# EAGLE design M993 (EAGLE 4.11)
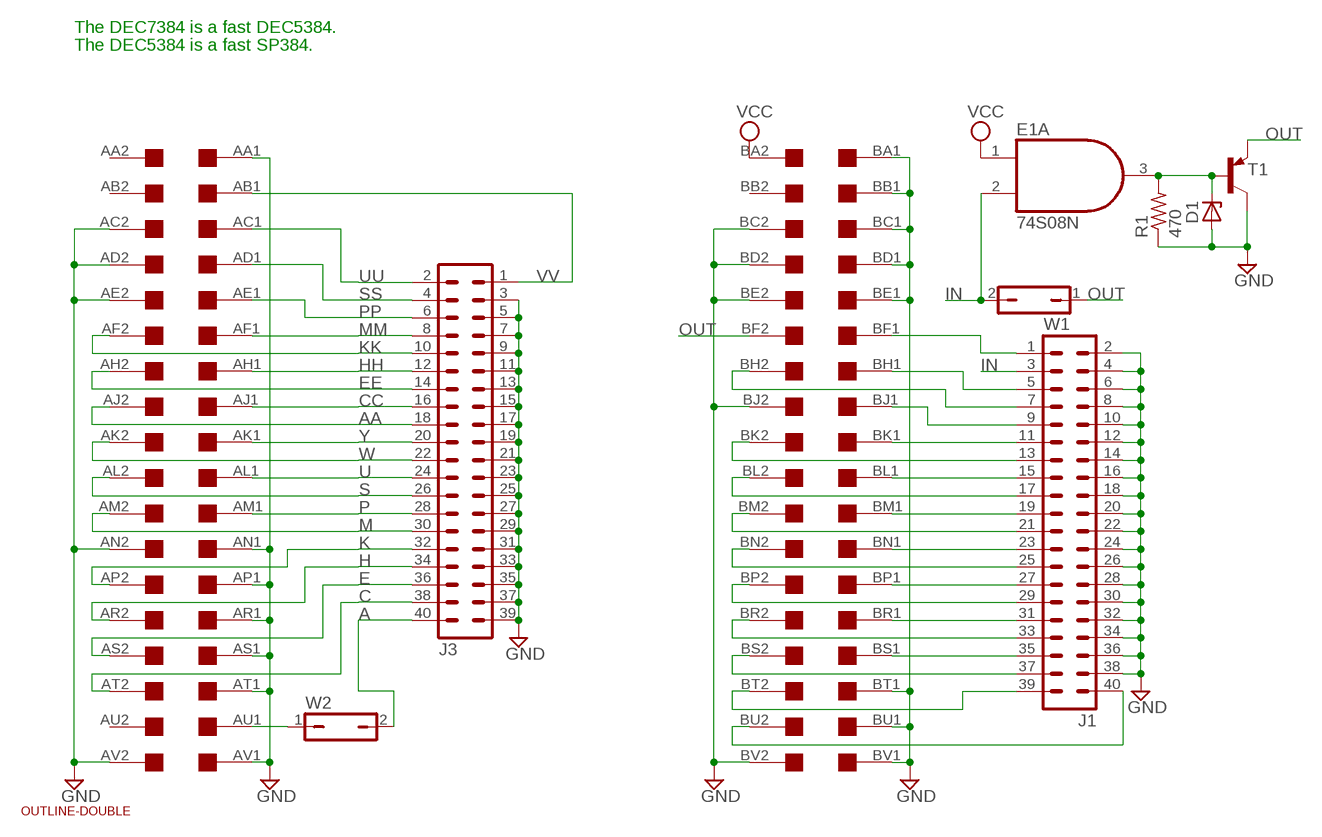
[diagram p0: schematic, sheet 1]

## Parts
D1  ZENER-DIODEZD-10  [ZDIO-10]
E1  74S08N  [DIL14]
J1  MA20-2  [MA20-2]
J3  MA20-2  [MA20-2]
R1  470  R-US_0207/10  [0207/10]
T1  -PNP-TO92  [TO92]
U$1  OUTLINE-DOUBLE  [DOUBLE]
U$2  DOUBLE  [EDGE-CON4]
W1  JP1Q  [JP1]
W2  JP1Q  [JP1]

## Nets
A: J3.40 W2.2
AA: J3.18 U$2.AJ2
C: J3.38 U$2.AT2
CC: J3.16 U$2.AJ1
E: J3.36 U$2.AS2
EE: J3.14 U$2.AH2
GND: D1.A J1.2 J1.4 J1.6 J1.8 J1.10 J1.12 J1.14 J1.16 J1.18 J1.20 J1.22 J1.24 J1.26 J1.28 J1.30 J1.32 J1.34 J1.36 J1.38 J3.3 J3.5 J3.7 J3.9 J3.11 J3.13 J3.15 J3.17 J3.19 J3.21 J3.23 J3.25 J3.27 J3.29 J3.31 J3.33 J3.35 J3.37 J3.39 R1.1 T1.3(C) U$2.AA1 U$2.AC2 U$2.AD2 U$2.AE2 U$2.AN1 U$2.AN2 U$2.AP1 U$2.AR1 U$2.AS1 U$2.AT1 U$2.AV1 U$2.AV2 U$2.BA1 U$2.BB1 U$2.BC1 U$2.BC2 U$2.BD1 U$2.BD2 U$2.BE1 U$2.BE2 U$2.BJ2 U$2.BT1 U$2.BU1 U$2.BV1 U$2.BV2
H: J3.34 U$2.AR2
HH: J3.12 U$2.AH1
IN: E1.2(A:I1) J1.3 W1.2
K: J3.32 U$2.AP2
KK: J3.10 U$2.AF2
M: J3.30 U$2.AM2
MM: J3.8 U$2.AF1
N$1: U$2.AU1 W2.1
N$2: D1.C E1.3(A:O) R1.2 T1.2(B)
N$3: J1.37 U$2.BS2
N$4: J1.35 U$2.BS1
N$5: J1.33 U$2.BR2
N$6: J1.31 U$2.BR1
N$7: J1.29 U$2.BP2
N$8: J1.27 U$2.BP1
N$9: J1.25 U$2.BN2
N$10: J1.40 U$2.BU2
N$11: J1.39 U$2.BT2
N$12: J1.23 U$2.BN1
N$13: J1.21 U$2.BM2
N$14: J1.19 U$2.BM1
N$15: J1.17 U$2.BL2
N$16: J1.15 U$2.BL1
N$17: J1.13 U$2.BK2
N$18: J1.11 U$2.BK1
N$19: J1.9 U$2.BJ1
N$20: J1.7 U$2.BH2
N$21: J1.5 U$2.BH1
N$23: J1.1 U$2.BF1
OUT: T1.1(E) U$2.BF2 W1.1
P: J3.28 U$2.AM1
PP: J3.6 U$2.AE1
S: J3.26 U$2.AL2
SS: J3.4 U$2.AD1
U: J3.24 U$2.AL1
UU: J3.2 U$2.AC1
VCC: E1.1(A:I0) U$2.BA2
VV: J3.1 U$2.AB1
W: J3.22 U$2.AK2
Y: J3.20 U$2.AK1
Unconnected: E1.4(B:I0) E1.5(B:I1) E1.6(B:O) E1.8(C:O) E1.9(C:I0) E1.10(C:I1) E1.11(D:O) E1.12(D:I0) E1.13(D:I1) U$2.AA2 U$2.AB2 U$2.AU2 U$2.BB2

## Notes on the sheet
- The DEC7384 is a fast DEC5384.
- The DEC5384 is a fast SP384.

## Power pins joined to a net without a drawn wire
GND: E1.7(P:GND)
VCC: E1.14(P:VCC)

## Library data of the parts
D1 = diode:ZENER-DIODE: Z-Diode
E1 = 74xx-us:74*08: Quad 2-input AND gate
J1 J3 = con-lstb:MA20-2: PIN HEADER
R1 = rcl:R-US_: RESISTOR, American symbol
T1 = transistor:*-PNP-: PNP Transistror
U$1 = dec-con:OUTLINE-*: Board outlines for DEC boards.
U$2 = dec-con:DOUBLE: Double-Height DEC board
W1 W2 = jumper:JP1Q: JUMPER

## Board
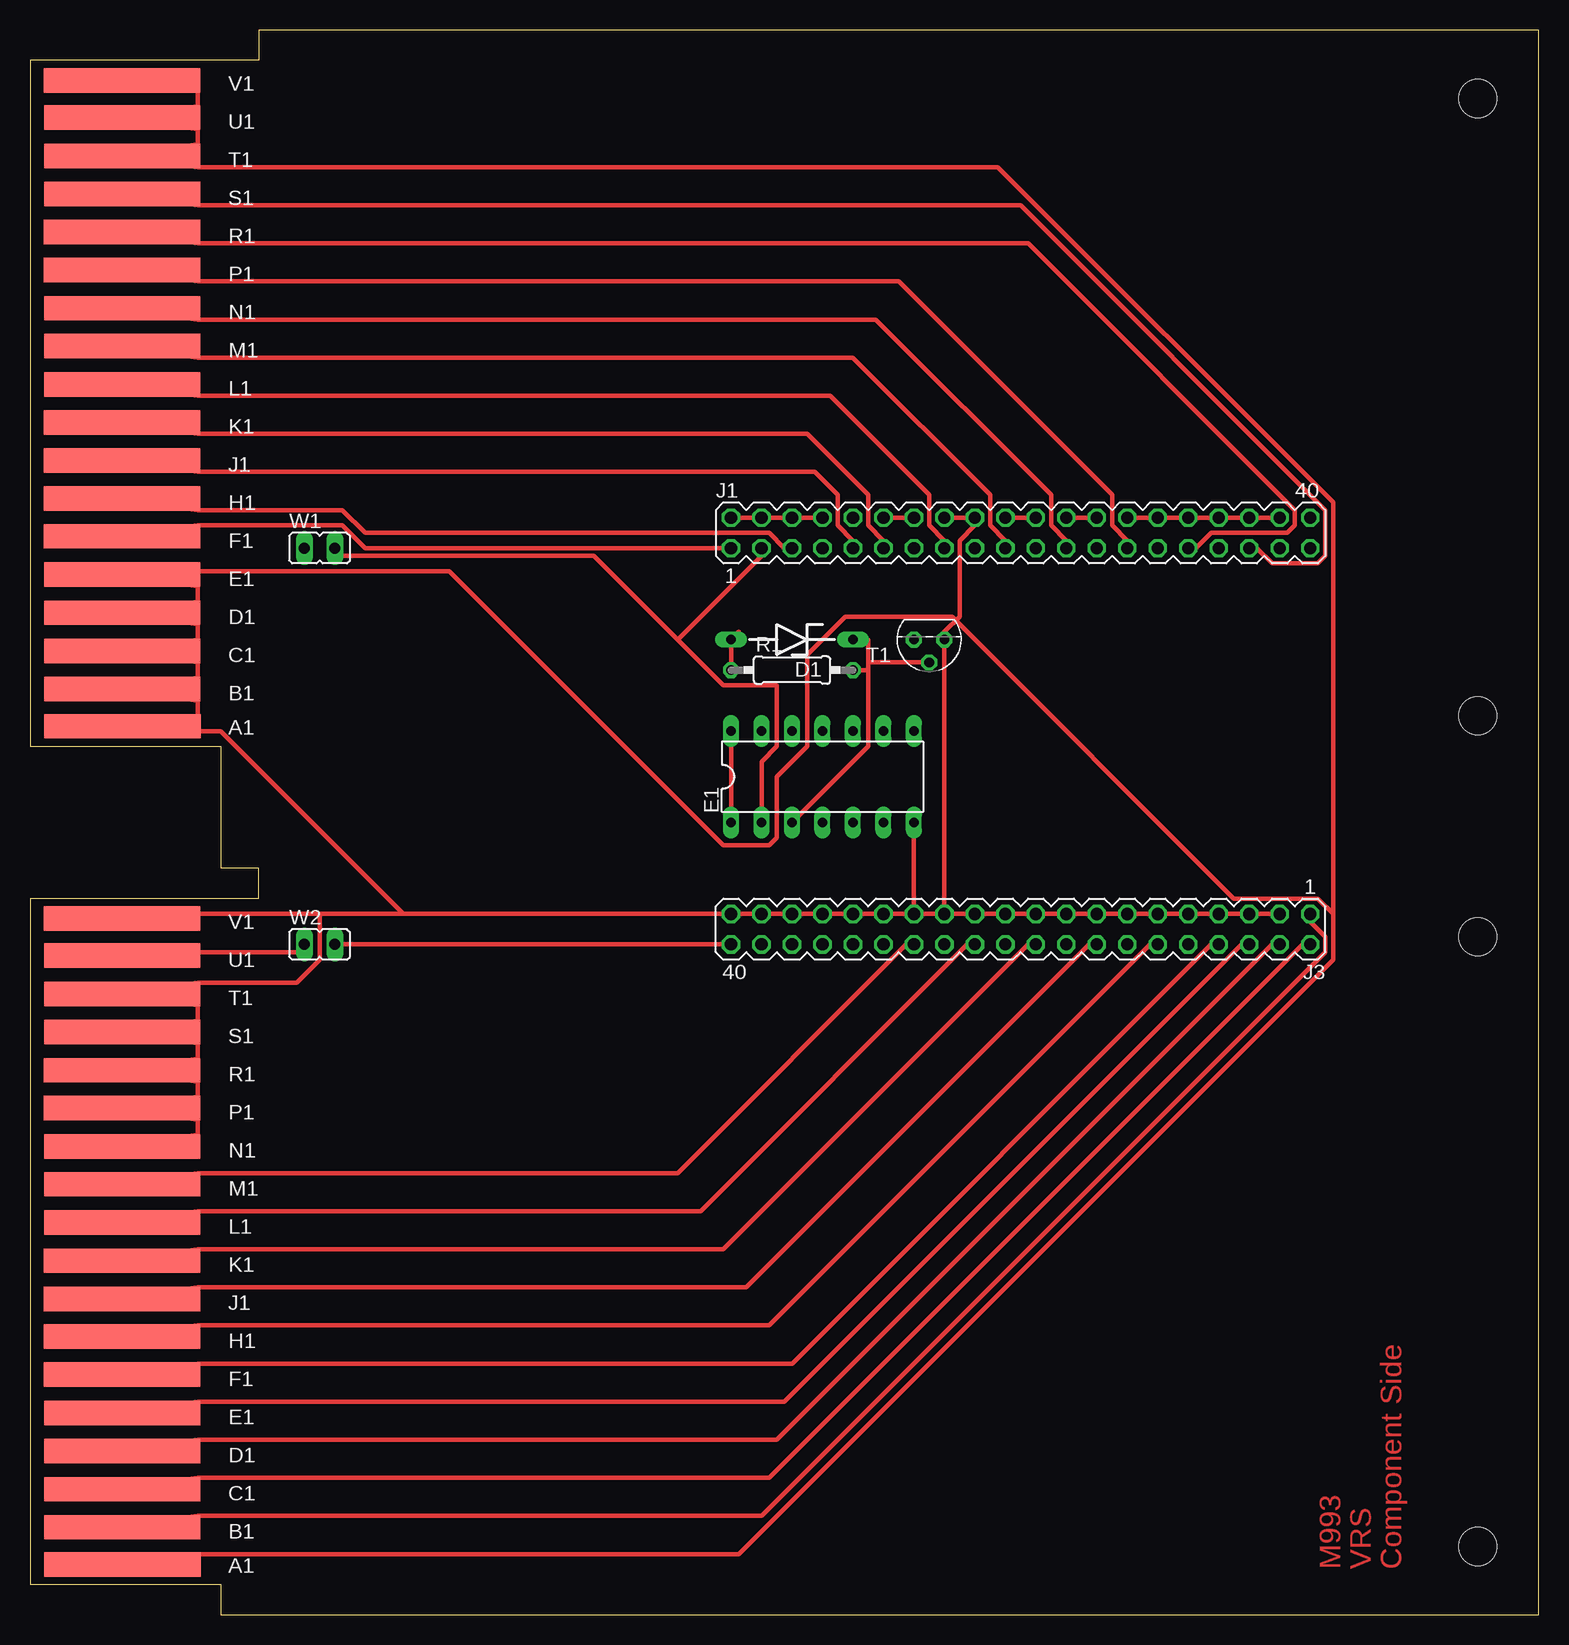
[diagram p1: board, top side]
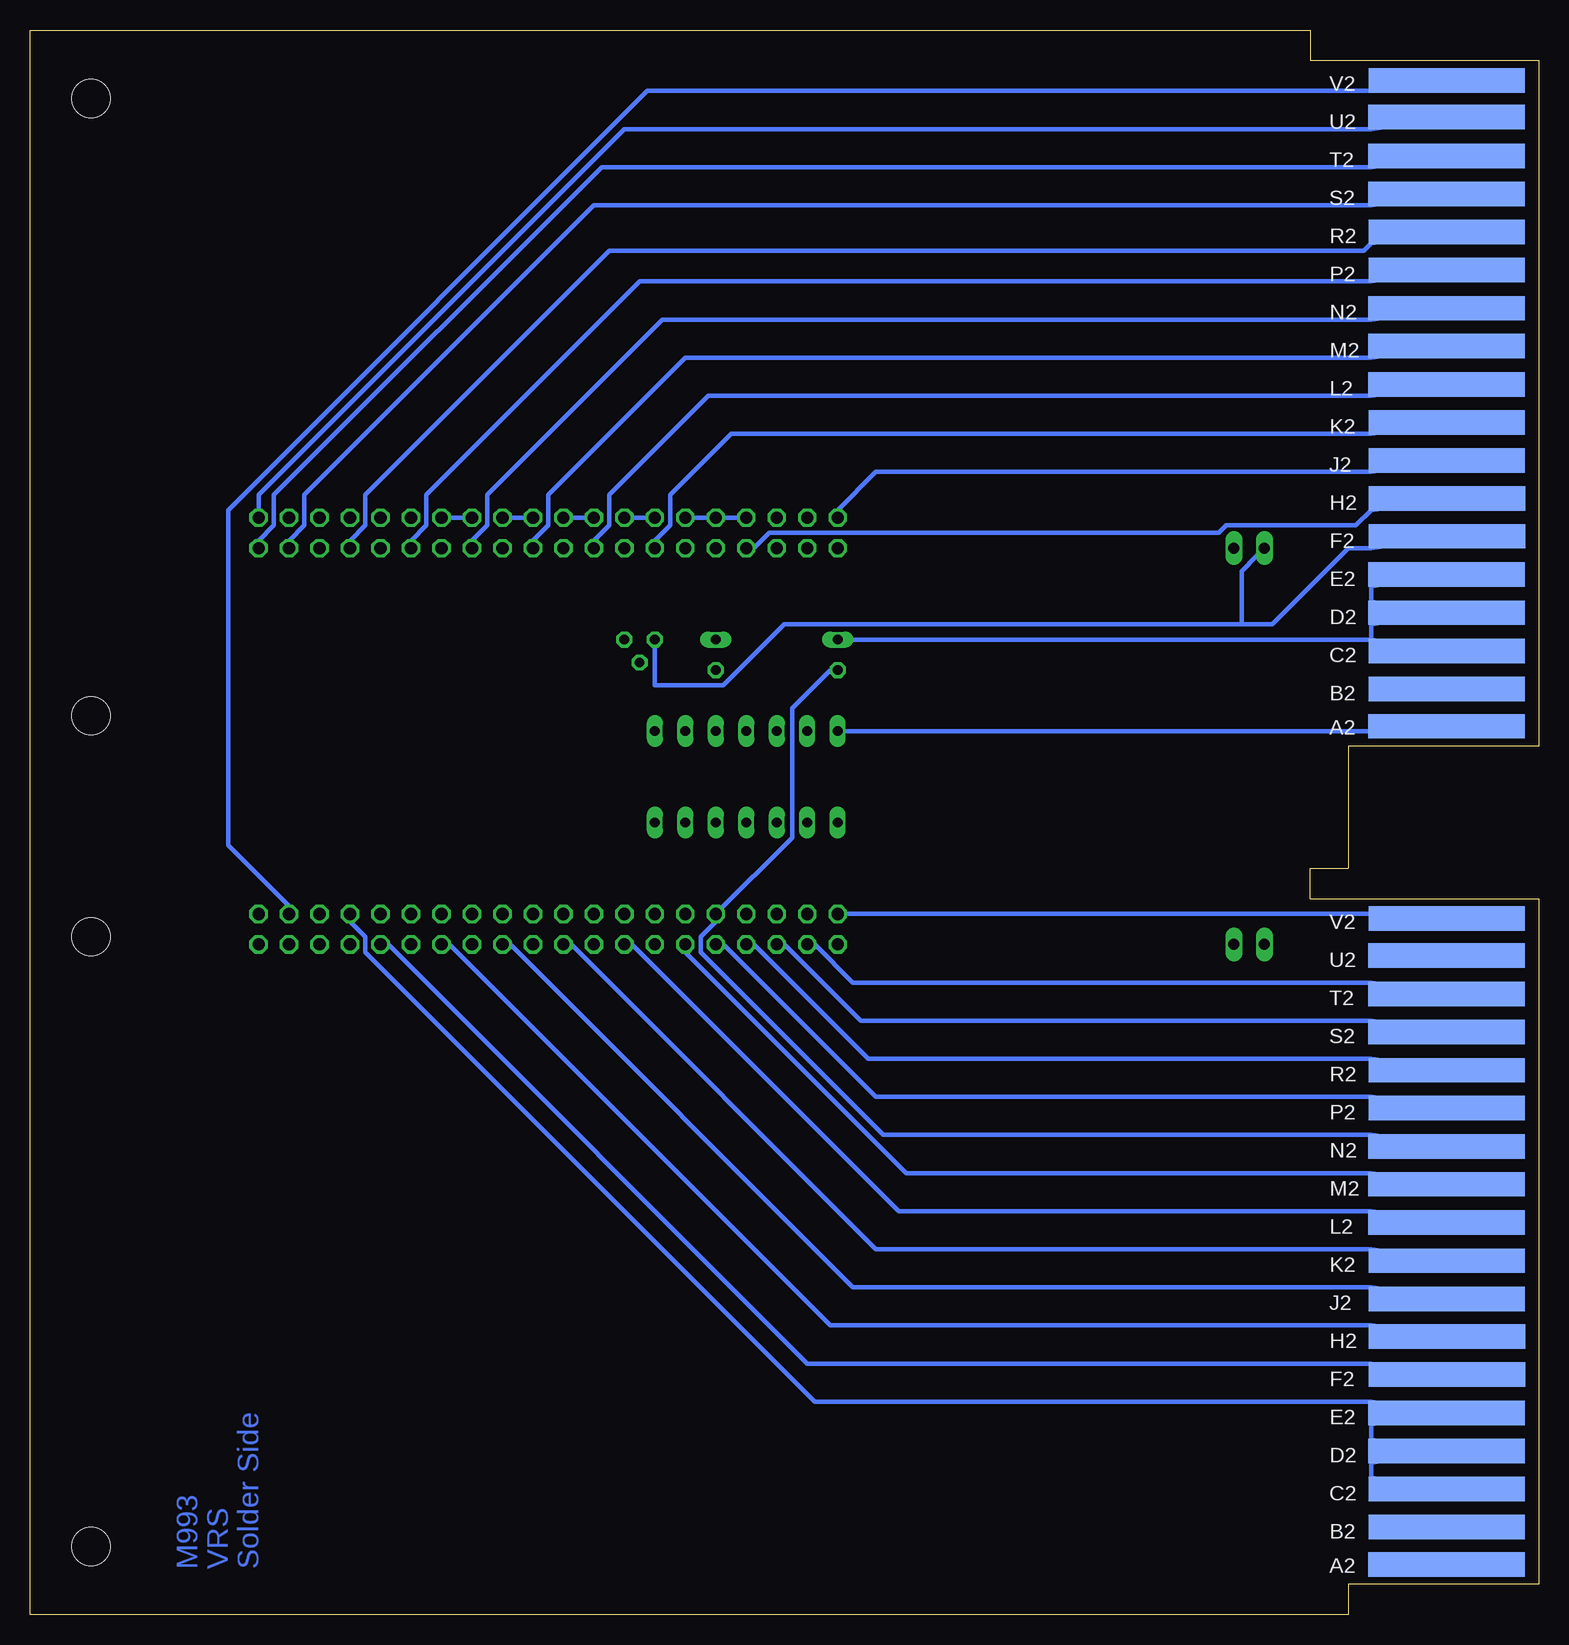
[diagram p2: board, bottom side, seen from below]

Size 125.73 x 132.08 mm. Coordinates in mm from the lower left corner, seen from the top.
Copper layers (1*16): Top 0.035mm / dielectric 1.5mm / Bottom 0.035mm
Design rules "default": minimum track width 15mil, minimum drill 24mil, track to track 8mil, track to pad 8mil, pad to pad 8mil, via to via 8mil, smd to smd 8mil, copper to edge 25mil, drill to drill 8mil, minimum pad ring 10mil, minimum via ring 8mil, stop-mask expansion 4mil, vias tented up to drill 0mil, thermal gap 10mil

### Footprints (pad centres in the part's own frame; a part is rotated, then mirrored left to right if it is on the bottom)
ZDIO-10 = drill 0.813 long: A 5.08,0; C -5.08,0
DIL14 = drill 0.813 long: 1 -7.62,-3.81; 2 -5.08,-3.81; 3 -2.54,-3.81; 4 0,-3.81; 5 2.54,-3.81; 6 5.08,-3.81; 7 7.62,-3.81; 8 7.62,3.81; 9 5.08,3.81; 10 2.54,3.81; 11 0,3.81; 12 -2.54,3.81; 13 -5.08,3.81; 14 -7.62,3.81
MA20-2 = drill 1.016 octagon: 1 -24.13,-1.27; 2 -24.13,1.27; 3 -21.59,-1.27; 4 -21.59,1.27; 5 -19.05,-1.27; 6 -19.05,1.27; 7 -16.51,-1.27; 8 -16.51,1.27; 9 -13.97,-1.27; 10 -13.97,1.27; 11 -11.43,-1.27; 12 -11.43,1.27; 13 -8.89,-1.27; 14 -8.89,1.27; 15 -6.35,-1.27; 16 -6.35,1.27; 17 -3.81,-1.27; 18 -3.81,1.27; 19 -1.27,-1.27; 20 -1.27,1.27; 21 1.27,-1.27; 22 1.27,1.27; 23 3.81,-1.27; 24 3.81,1.27; 25 6.35,-1.27; 26 6.35,1.27; 27 8.89,-1.27; 28 8.89,1.27; 29 11.43,-1.27; 30 11.43,1.27; 31 13.97,-1.27; 32 13.97,1.27; 33 16.51,-1.27; 34 16.51,1.27; 35 19.05,-1.27; 36 19.05,1.27; 37 21.59,-1.27; 38 21.59,1.27; 39 24.13,-1.27; 40 24.13,1.27
0207/10 = drill 0.813 octagon: 1 -5.08,0; 2 5.08,0
TO92 = drill 0.813 octagon: 1 1.27,0; 2 0,1.905; 3 -1.27,0
DOUBLE = hole 3.175: 120.65,56.515; 120.65,5.715; 120.65,74.93; 120.65,126.365
EDGE-CON4 = smd 13.017 x 2.032: AA1 7.709,4.207; AB1 7.684,7.312; AC1 7.684,10.474; AD1 7.684,13.665; AE1 7.693,16.84; AF1 7.668,20.041; AH1 7.668,23.19; AJ1 7.668,26.34; AK1 7.668,29.515; AL1 7.693,32.69; AM1 7.693,35.89; AN1 7.693,39.04; AP1 7.668,42.24; AR1 7.668,45.39; AS1 7.693,48.565; AT1 7.693,51.74; AU1 7.693,54.94; AV1 7.668,58.026; BA1 7.709,74.057; BB1 7.684,77.162; BC1 7.684,80.324; BD1 7.684,83.515; BE1 7.693,86.69; BF1 7.668,89.891; BH1 7.668,93.04; BJ1 7.668,96.19; BK1 7.668,99.365; BL1 7.693,102.54; BM1 7.693,105.74; BN1 7.693,108.89; BP1 7.668,112.09; BR1 7.668,115.24; BS1 7.693,118.415; BT1 7.693,121.59; BU1 7.693,124.79; BV1 7.668,127.876 | smd 13.017 x 2.032 bottom: AA2 7.69,4.207; AB2 7.668,7.328; AC2 7.668,10.49; AD2 7.693,13.665; AE2 7.693,16.84; AF2 7.642,20.041; AH2 7.642,23.19; AJ2 7.668,26.34; AK2 7.668,29.515; AL2 7.693,32.69; AM2 7.693,35.89; AN2 7.693,39.04; AP2 7.668,42.24; AR2 7.668,45.39; AS2 7.693,48.565; AT2 7.693,51.74; AU2 7.693,54.966; AV2 7.668,58.026; BA2 7.69,74.057; BB2 7.668,77.178; BC2 7.668,80.34; BD2 7.693,83.515; BE2 7.693,86.69; BF2 7.642,89.891; BH2 7.642,93.04; BJ2 7.668,96.19; BK2 7.668,99.365; BL2 7.693,102.54; BM2 7.693,105.74; BN2 7.693,108.89; BP2 7.668,112.09; BR2 7.668,115.24; BS2 7.693,118.415; BT2 7.693,121.59; BU2 7.693,124.816; BV2 7.668,127.876
JP1 = drill 0.914 long: 1 0,-1.27; 2 0,1.27

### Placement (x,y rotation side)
D1  63.5,81.28 180 top
E1  66.04,69.85 0 top
J1  82.55,90.17 0 top
J3  82.55,57.15 180 top
R1  63.5,78.74 0 top
T1  74.93,81.28 180 top
U$1  0,0 0 top
U$2  0,0 0 top
W1  24.13,88.9 270 top
W2  24.13,55.88 270 top

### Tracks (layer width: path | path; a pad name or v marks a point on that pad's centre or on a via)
A
  Top 0.381: W2.2 26.04,55.88 57.79,55.88 J3.40
AA
  Bottom 0.381: J3.18 85.73,55.88 57.15,27.3 13.97,27.3 U$2.AJ2
C
  Bottom 0.381: J3.38 60.33,55.88 57.15,52.7 13.97,52.7 U$2.AT2
CC
  Top 0.381: J3.16 88.27,55.88 59.69,27.3 13.97,27.3 U$2.AJ1
E
  Bottom 0.381: J3.36 62.87,55.88 56.52,49.53 13.97,49.53 U$2.AS2
EE
  Bottom 0.381: J3.14 90.81,55.88 59.06,24.13 13.97,24.13 U$2.AH2
GND
  Top 0.381: U$2.BV1 13.97,127 13.97,125.73 U$2.BU1 13.97,123.83 13.97,122.56 U$2.BT1 13.97,120.65 80.65,120.65 108.59,92.71 108.59,58.42 | R1.1 D1.A 59.06,81.92 | J3.27 E1.7 | J3.27 J3.25 | J3.25 J3.23 J3.21 J3.19 J3.17 J3.15 J3.13 J3.11 J3.9 J3.7 J3.5 J3.3 | J3.27 J3.29 J3.31 J3.33 J3.35 J3.37 J3.39 31.12,58.42 | 31.12,58.42 24.13,58.42 | 24.13,58.42 13.97,58.42 U$2.AV2 | U$2.AA1 13.97,5.08 59.06,5.08 108.59,54.61 108.59,58.42 | 31.12,58.42 15.88,73.66 13.97,73.66 U$2.BA1 13.97,74.93 13.97,76.2 U$2.BB1 13.97,78.11 13.97,79.38 U$2.BC1 13.97,81.28 13.97,82.55 U$2.BD1 13.97,84.45 13.97,85.72 U$2.BE1 13.97,87 34.93,87 57.79,64.14 61.6,64.14 62.23,64.77 62.23,69.85 64.77,72.39 64.77,80.01 67.95,83.19 76.84,83.19 100.33,59.69 107.32,59.69 108.59,58.42 | 24.13,58.42 24.13,54.61 22.23,52.7 13.97,52.7 U$2.AT1 13.97,50.8 13.97,49.53 U$2.AS1 13.97,47.62 13.97,46.35 U$2.AR1 13.97,44.45 13.97,43.18 U$2.AP1 13.97,41.27 13.97,40.01 U$2.AN2 | J3.25 T1.3 76.2,81.92 77.47,83.19 77.47,89.53 78.74,90.81 J1.18 J1.16 | J1.2 J1.4 J1.6 J1.8 | J1.14 J1.12 | J1.20 J1.22 | J1.24 J1.26 | J1.28 J1.30 J1.32 J1.34 J1.36 J1.38
  Bottom 0.381: 13.97,81.28 13.97,82.55 U$2.BD2 13.97,84.45 13.97,85.72 U$2.BE1 | U$2.BJ2 13.97,95.25 55.25,95.25 58.42,92.08 J1.2 | 13.97,81.28 U$2.BC2 | D1.A 13.97,81.28 | U$2.AC2 13.97,11.43 13.97,12.7 U$2.AD2 13.97,14.61 13.97,15.88 U$2.AE2 13.97,17.78 60.33,17.78 97.79,55.24 97.79,56.52 99.06,57.78 J3.7 | U$2.AV2 13.97,58.42 J3.39 | U$2.AN2 13.97,40.01 54.61,40.01 69.85,55.24 69.85,56.52 68.58,57.78 J3.31 62.23,64.77 62.23,75.56 59.06,78.74 R1.1 | U$2.BV1 13.97,127 74.3,127 109.22,92.08 109.22,64.14 104.14,59.05 J3.3 | J1.8 J1.10 J1.12 | J1.16 J1.14 | J1.18 J1.20 | J1.22 J1.24 | J1.26 J1.28
H
  Bottom 0.381: J3.34 65.41,55.88 55.88,46.35 13.97,46.35 U$2.AR2
HH
  Top 0.381: J3.12 93.35,55.88 61.6,24.13 13.97,24.13 U$2.AH1
IN
  Top 0.381: 53.98,81.28 46.99,88.27 26.04,88.27 W1.2 | 53.98,81.28 57.79,77.47 62.23,77.47 62.23,72.39 60.96,71.12 60.96,67.31 E1.2 | 53.98,81.28 60.96,88.27 J1.3
K
  Bottom 0.381: J3.32 67.95,55.88 55.25,43.18 13.97,43.18 U$2.AP2
KK
  Bottom 0.381: J3.10 95.89,55.88 60.96,20.95 13.97,20.95 U$2.AF2
M
  Bottom 0.381: J3.30 71.12,55.24 52.71,36.83 13.97,36.83 U$2.AM2
MM
  Top 0.381: J3.8 98.43,55.88 63.5,20.95 13.97,20.95 U$2.AF1
N$1
  Top 0.381: W2.1 22.23,55.24 13.97,55.24 U$2.AU1
N$2
  Top 0.381: 69.85,79.38 69.85,81.28 D1.C | 69.85,78.74 69.85,79.38 | 69.85,78.74 69.85,72.39 64.14,66.67 E1.3 | 69.85,78.74 69.22,78.74 R1.2 | 69.85,79.38 74.3,79.38 T1.2
N$3
  Bottom 0.381: U$2.BS2 13.97,117.47 78.74,117.47 102.87,93.34 102.87,90.81 104.14,89.53 J1.37
N$4
  Top 0.381: U$2.BS1 13.97,117.47 76.2,117.47 82.55,117.47 107.95,92.08 107.95,88.27 107.32,87.63 103.51,87.63 102.24,88.9 J1.35
N$5
  Bottom 0.381: U$2.BR2 13.97,114.3 14.61,113.67 77.47,113.67 97.79,93.34 97.79,90.81 99.06,89.53 J1.33
N$6
  Top 0.381: U$2.BR1 13.97,114.3 74.3,114.3 83.19,114.3 105.41,92.08 105.41,90.81 104.78,90.17 98.43,90.17 97.16,88.9 J1.31
N$7
  Bottom 0.381: U$2.BP2 13.97,111.12 74.93,111.12 92.71,93.34 92.71,90.81 93.98,89.53 J1.29
N$8
  Top 0.381: U$2.BP1 13.97,111.12 72.39,111.12 90.17,93.34 90.17,90.81 91.44,89.53 J1.27
N$9
  Bottom 0.381: U$2.BN2 13.97,107.95 73.03,107.95 87.63,93.34 87.63,90.81 88.9,89.53 J1.25
N$10
  Bottom 0.381: U$2.BU2 13.97,123.83 76.2,123.83 106.68,93.34 106.68,92.08 J1.40
N$11
  Bottom 0.381: U$2.BT2 13.97,120.65 78.11,120.65 105.41,93.34 105.41,90.81 106.68,89.53 J1.39
N$12
  Top 0.381: U$2.BN1 13.97,107.95 70.49,107.95 85.09,93.34 85.09,90.81 86.36,89.53 J1.23
N$13
  Bottom 0.381: U$2.BM2 13.97,104.78 71.12,104.78 82.55,93.34 82.55,90.81 83.82,89.53 J1.21
N$14
  Top 0.381: U$2.BM1 13.97,104.78 68.58,104.78 80.01,93.34 80.01,90.81 81.28,89.53 J1.19
N$15
  Bottom 0.381: U$2.BL2 13.97,101.6 69.22,101.6 77.47,93.34 77.47,90.81 78.74,89.53 J1.17
N$16
  Top 0.381: U$2.BL1 13.97,101.6 66.68,101.6 74.93,93.34 74.93,90.81 76.2,89.53 J1.15
N$17
  Bottom 0.381: U$2.BK2 13.97,98.42 67.31,98.42 72.39,93.34 72.39,90.81 73.66,89.53 J1.13
N$18
  Top 0.381: U$2.BK1 13.97,98.42 64.77,98.42 69.85,93.34 69.85,90.81 71.12,89.53 J1.11
N$19
  Top 0.381: U$2.BJ1 13.97,95.25 65.41,95.25 67.31,93.34 67.31,90.81 68.58,89.53 J1.9
N$20
  Bottom 0.381: U$2.BH2 13.97,92.08 15.24,90.81 26.04,90.81 26.67,90.17 64.14,90.17 65.41,88.9 J1.7
N$21
  Top 0.381: 13.97,92.71 U$2.BH1 13.97,92.08 26.04,92.08 27.94,90.17 61.6,90.17 62.87,88.9 J1.5
N$23
  Top 0.381: U$2.BF1 13.97,90.81 26.04,90.81 27.94,88.9 57.79,88.9 J1.1
OUT
  Bottom 0.381: W1.1 23.5,88.27 24.77,87 24.77,82.55 | 24.77,82.55 22.23,82.55 15.88,88.9 13.97,88.9 U$2.BF2 | 24.77,82.55 62.87,82.55 67.95,77.47 73.66,77.47 73.66,80.64 T1.1
P
  Top 0.381: J3.28 73.03,55.88 53.98,36.83 13.97,36.83 U$2.AM1
PP
  Top 0.381: J3.6 100.97,55.88 62.87,17.78 13.97,17.78 U$2.AE1
S
  Bottom 0.381: J3.26 75.57,55.88 53.34,33.66 13.97,33.66 U$2.AL2
SS
  Top 0.381: J3.4 103.51,55.88 62.23,14.61 13.97,14.61 U$2.AD1
U
  Top 0.381: J3.24 78.11,55.88 55.88,33.66 13.97,33.66 U$2.AL1
UU
  Top 0.381: J3.2 106.05,55.88 61.6,11.43 13.97,11.43 U$2.AC1
VCC
  Top 0.381: E1.14 58.42,72.39 58.42,67.31 E1.1
  Bottom 0.381: E1.14 57.79,73.66 13.97,73.66 U$2.BA2
VV
  Top 0.381: J3.1 106.68,57.78 107.95,56.52 107.95,55.24 60.96,8.26 13.97,8.26 U$2.AB1
W
  Bottom 0.381: J3.22 80.65,55.88 55.25,30.48 13.97,30.48 U$2.AK2
Y
  Top 0.381: J3.20 83.19,55.88 57.79,30.48 13.97,30.48 U$2.AK1

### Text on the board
Top: M993 | VRS | Component Side
Bottom: Solder Side | VRS | M993
tValues: A | VV | A | VV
